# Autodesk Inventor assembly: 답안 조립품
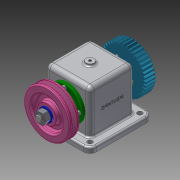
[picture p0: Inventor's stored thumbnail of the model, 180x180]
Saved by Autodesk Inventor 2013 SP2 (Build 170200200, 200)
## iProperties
Created: 2022-07
Part Number: 답안 조립품
Document SubType Name: Assembly
Designer: i
Author: i
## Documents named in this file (12)
- C:\Users\i\Desktop\720706V1013\답안 조립품.iam
- C:\Users\i\Desktop\720706V1013\본체.ipt
- C:\Users\i\Desktop\720706V1013\V벨트풀리.ipt
- C:\Users\i\Desktop\720706V1013\너트 M12x1.25.ipt
- C:\Users\i\Desktop\720706V1013\베어링 6204.ipt
- C:\Users\i\Desktop\720706V1013\볼트 M4x0.7.ipt
- C:\Users\i\Desktop\720706V1013\스퍼기어.ipt
- C:\Users\i\Desktop\720706V1013\오일실 20x35x8.ipt
- C:\Users\i\Desktop\720706V1013\와셔 12x24.ipt
- C:\Users\i\Desktop\720706V1013\축.ipt
- C:\Users\i\Desktop\720706V1013\커버.ipt
- C:\Users\i\Desktop\720706V1013\키 5x5.ipt
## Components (1 placed, 1 different names)
1. V벨트풀리:1
